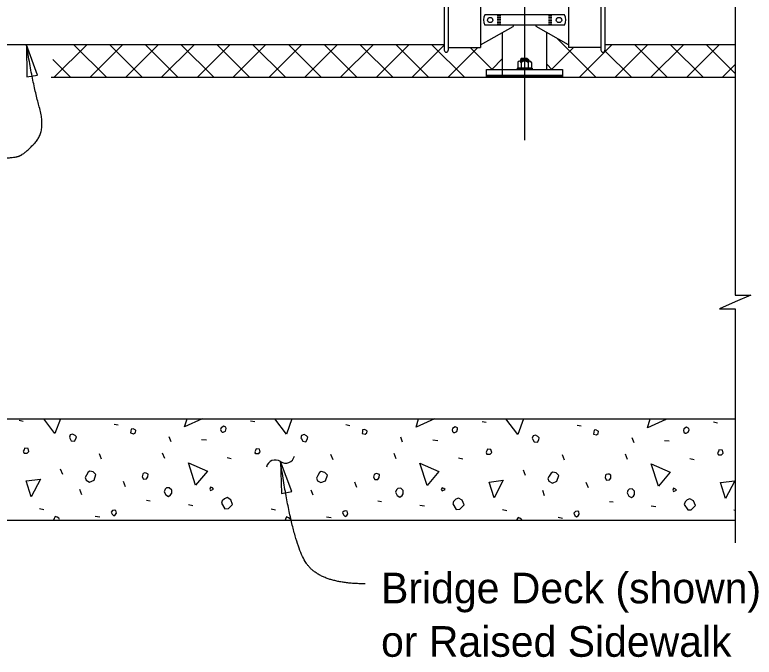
# Model space of a CAD drawing. Extents: x 110698 to 110915, y 110390 to 110472.
# Drawn here: x 110792.784 to 110797.653, y 110451.994 to 110456.224 of the extents above; entities that cross this region are included whole.
import ezdxf

# ---------------------------------------------------------------- set-up
doc = ezdxf.new("R2010")
doc.units = 0
for name, color, linetype in [('AdhocPoint_dp', 7, 'Continuous'), ('PlotBorder_dp', 7, 'Continuous'), ('SheetBorder_dp', 7, 'Continuous'), ('SheetLines_dp', 7, 'Continuous'), ('TextMisc', 7, 'Continuous')]:
    doc.layers.add(name, color=color, linetype=linetype)

msp = doc.modelspace()

# ---------------------------------------------------------------- linework, layer by layer
at = {"layer": 'AdhocPoint_dp'}
msp.add_line((110796.1408, 110464.1815), (110796.1408, 110455.3996), dxfattribs=at)
at = {"layer": 'PlotBorder_dp'}
msp.add_line((110796.1408, 110455.8731), (110796.1408, 110455.8724), dxfattribs=at)
for points in [[(110797.5278, 110458.8754), (110797.5278, 110457.8577), (110797.6311, 110457.8577), (110797.5278, 110457.8127), (110797.4245, 110457.7677), (110797.5278, 110457.7677), (110797.5278, 110455.8133)], [(110797.5278, 110455.8133), (110797.5278, 110454.3793), (110797.6311, 110454.3793), (110797.5278, 110454.3343), (110797.4245, 110454.2893), (110797.5278, 110454.2893), (110797.5278, 110452.7468)]]:
    msp.add_lwpolyline(points, dxfattribs=at)
for points in [[(110792.8618, 110456.0268), (110792.8634, 110455.8156), (110792.9329, 110455.8279)], [(110794.5338, 110453.2829), (110794.5399, 110453.0717), (110794.6091, 110453.0855)]]:
    msp.add_lwpolyline(points, close=True, dxfattribs=at)
for centre, start, end in [((110794.4992, 110453.2334), 55.4525, 167.1798), ((110794.5668, 110453.3316), 235.4525, 347.1798)]:
    msp.add_arc(centre, 0.0596, start, end, dxfattribs=at)
for points in [[(110792.5505, 110455.2798), (110792.7733, 110455.2763), (110792.8582, 110455.3152), (110792.9891, 110455.4639), (110792.9042, 110455.7614), (110792.8618, 110456.0267)], [(110795.0922, 110452.4775), (110794.8036, 110452.4775), (110794.6145, 110452.733), (110794.5338, 110453.2829)]]:
    msp.add_open_spline(points, degree=2, dxfattribs=at)
at = {"layer": 'SheetBorder_dp'}
for p, q in [((110796.35, 110456.0722), (110796.6089, 110455.8133)), ((110793.044, 110455.8133), (110793.2575, 110456.0268)), ((110793.1736, 110456.0268), (110793.3871, 110455.8133)), ((110793.2797, 110455.8133), (110793.4932, 110456.0268)), ((110793.4093, 110456.0268), (110793.6228, 110455.8133)), ((110793.5154, 110455.8133), (110793.7289, 110456.0268)), ((110793.645, 110456.0268), (110793.8585, 110455.8133)), ((110793.7511, 110455.8133), (110793.9646, 110456.0268)), ((110793.8807, 110456.0268), (110794.0942, 110455.8133)), ((110793.9868, 110455.8133), (110794.2003, 110456.0268)), ((110794.1164, 110456.0268), (110794.3299, 110455.8133)), ((110794.2225, 110455.8133), (110794.436, 110456.0268)), ((110794.3521, 110456.0268), (110794.5656, 110455.8133)), ((110794.4582, 110455.8133), (110794.6717, 110456.0268)), ((110794.5878, 110456.0268), (110794.8013, 110455.8133)), ((110794.6939, 110455.8133), (110794.9074, 110456.0268)), ((110794.8235, 110456.0268), (110795.0371, 110455.8133)), ((110794.9296, 110455.8133), (110795.1431, 110456.0268)), ((110795.0592, 110456.0268), (110795.2728, 110455.8133)), ((110795.1653, 110455.8133), (110795.3788, 110456.0268)), ((110795.2949, 110456.0268), (110795.5085, 110455.8133)), ((110795.401, 110455.8133), (110795.6114, 110456.0237)), ((110795.5306, 110456.0268), (110795.7442, 110455.8133)), ((110795.6367, 110455.8133), (110795.833, 110456.0096)), ((110795.7836, 110456.0096), (110795.9278, 110455.8653)), ((110796.3179, 110455.8653), (110796.4621, 110456.0096)), ((110796.5015, 110455.8133), (110796.715, 110456.0268)), ((110796.7372, 110455.8133), (110796.9507, 110456.0268)), ((110796.8668, 110456.0268), (110797.0803, 110455.8133)), ((110796.9729, 110455.8133), (110797.1864, 110456.0268)), ((110797.1025, 110456.0268), (110797.316, 110455.8133)), ((110797.2086, 110455.8133), (110797.4221, 110456.0268)), ((110797.3382, 110456.0268), (110797.5277, 110455.8373)), ((110796.6701, 110455.9878), (110796.8446, 110455.8133)), ((110793.034, 110455.9307), (110793.1514, 110455.8133)), ((110795.9245, 110455.8653), (110795.995, 110455.9358)), ((110796.1296, 110455.9348), (110796.1503, 110455.9348)), ((110796.1296, 110455.9251), (110796.1503, 110455.9251)), ((110796.2899, 110455.8966), (110796.3212, 110455.8653)), ((110797.4443, 110455.8133), (110797.5277, 110455.8967)), ((110795.8908, 110455.8202), (110796.3908, 110455.8202)), ((110795.8908, 110455.8167), (110796.3908, 110455.8167)), ((110792.8134, 110453.5542), (110792.8399, 110453.5489)), ((110793.4391, 110453.5294), (110793.4657, 110453.5241)), ((110794.3372, 110453.5507), (110794.3637, 110453.5453)), ((110794.963, 110453.5259), (110794.9895, 110453.5206)), ((110795.861, 110453.5471), (110795.8875, 110453.5418)), ((110797.3848, 110453.5436), (110797.4113, 110453.5383)), ((110796.4868, 110453.5224), (110796.5133, 110453.5171)), ((110793.8139, 110453.4128), (110793.8015, 110453.4464)), ((110794.0137, 110453.4287), (110794.0455, 110453.4251)), ((110795.3377, 110453.4092), (110795.3254, 110453.4428)), ((110796.8615, 110453.4057), (110796.8492, 110453.4393)), ((110795.5375, 110453.4251), (110795.5693, 110453.4216)), ((110797.0613, 110453.4216), (110797.0931, 110453.4181)), ((110793.3561, 110453.2979), (110793.3419, 110453.3332)), ((110793.7715, 110453.3032), (110793.7573, 110453.3385)), ((110794.8799, 110453.2943), (110794.8657, 110453.3297)), ((110795.2953, 110453.2996), (110795.2812, 110453.335)), ((110796.8191, 110453.2961), (110796.805, 110453.3314)), ((110794.1816, 110453.3102), (110794.2099, 110453.3032)), ((110795.7054, 110453.3067), (110795.7337, 110453.2996)), ((110796.4037, 110453.2908), (110796.3896, 110453.3261)), ((110797.2292, 110453.3032), (110797.2575, 110453.2961)), ((110793.0997, 110453.1971), (110793.0856, 110453.2325)), ((110796.1474, 110453.19), (110796.1332, 110453.2254)), ((110793.5134, 110453.1158), (110793.4993, 110453.1511)), ((110795.0372, 110453.1122), (110795.0231, 110453.1476)), ((110796.561, 110453.1087), (110796.5469, 110453.1441)), ((110793.2252, 110453.0645), (110793.2129, 110453.0981)), ((110794.7491, 110453.061), (110794.7367, 110453.0946)), ((110796.2729, 110453.0574), (110796.2605, 110453.091)), ((110793.6513, 110453.0274), (110793.676, 110453.0239)), ((110793.9271, 110452.9991), (110793.9571, 110452.9938)), ((110795.1751, 110453.0239), (110795.1998, 110453.0203)), ((110795.4509, 110452.9956), (110795.4809, 110452.9903)), ((110796.6989, 110453.0203), (110796.7237, 110453.0168)), ((110796.9747, 110452.992), (110797.0047, 110452.9867)), ((110792.9477, 110452.9744), (110792.976, 110452.9673)), ((110794.4715, 110452.9708), (110794.4998, 110452.9638)), ((110795.9953, 110452.9673), (110796.0236, 110452.9602)), ((110797.5192, 110452.9638), (110797.5277, 110452.9616)), ((110793.3136, 110452.9231), (110793.3437, 110452.9178)), ((110794.0638, 110452.8966), (110794.0632, 110452.8983)), ((110794.8375, 110452.9196), (110794.8675, 110452.9143)), ((110796.3613, 110452.916), (110796.3913, 110452.9107))]:
    msp.add_line(p, q, dxfattribs=at)
msp.add_lwpolyline([(110795.8908, 110455.8237), (110796.3908, 110455.8237), (110796.3908, 110455.8133), (110795.8908, 110455.8133)], close=True, dxfattribs=at)
for points in [[(110793.0485, 110453.4676), (110792.9758, 110453.5632)], [(110793.0842, 110453.5632), (110793.0485, 110453.4676)], [(110793.9023, 110453.5118), (110793.9181, 110453.5632)], [(110794.0169, 110453.5632), (110793.9023, 110453.5118)], [(110794.5723, 110453.464), (110794.4969, 110453.5632)], [(110794.6094, 110453.5632), (110794.5723, 110453.464)], [(110795.4261, 110453.5082), (110795.443, 110453.5632)], [(110795.5475, 110453.5632), (110795.5481, 110453.563), (110795.4261, 110453.5082)], [(110796.0961, 110453.4605), (110796.018, 110453.5632)], [(110796.1345, 110453.5632), (110796.0961, 110453.4605)], [(110796.9499, 110453.5047), (110796.9679, 110453.5632)], [(110797.0624, 110453.5632), (110797.0719, 110453.5595), (110796.9499, 110453.5047)], [(110793.547, 110453.4711), (110793.5664, 110453.4658), (110793.5788, 110453.4746), (110793.5806, 110453.487), (110793.577, 110453.4905), (110793.5629, 110453.4976), (110793.5505, 110453.4959), (110793.5487, 110453.4835), (110793.547, 110453.4711)], [(110794.1498, 110453.4764), (110794.1569, 110453.4764), (110794.171, 110453.4835), (110794.1763, 110453.4994), (110794.1745, 110453.5082), (110794.1604, 110453.5153), (110794.1427, 110453.5047), (110794.1392, 110453.4941), (110794.1427, 110453.4835), (110794.1498, 110453.4764)], [(110795.0708, 110453.4676), (110795.0902, 110453.4623), (110795.1026, 110453.4711), (110795.1044, 110453.4835), (110795.1008, 110453.487), (110795.0867, 110453.4941), (110795.0743, 110453.4923), (110795.0726, 110453.4799), (110795.0708, 110453.4676)], [(110795.6736, 110453.4729), (110795.6807, 110453.4729), (110795.6948, 110453.4799), (110795.7001, 110453.4959), (110795.6984, 110453.5047), (110795.6842, 110453.5118), (110795.6665, 110453.5012), (110795.663, 110453.4905), (110795.6665, 110453.4799), (110795.6736, 110453.4729)], [(110796.5946, 110453.464), (110796.6141, 110453.4587), (110796.6264, 110453.4676), (110796.6282, 110453.4799), (110796.6247, 110453.4835), (110796.6105, 110453.4905), (110796.5981, 110453.4888), (110796.5964, 110453.4764), (110796.5946, 110453.464)], [(110797.1974, 110453.4693), (110797.2045, 110453.4693), (110797.2186, 110453.4764), (110797.2239, 110453.4923), (110797.2222, 110453.5012), (110797.208, 110453.5082), (110797.1903, 110453.4976), (110797.1868, 110453.487), (110797.1903, 110453.4764), (110797.1974, 110453.4693)], [(110793.1475, 110453.4357), (110793.1563, 110453.4198), (110793.1775, 110453.4163), (110793.1864, 110453.4322), (110793.1899, 110453.4464), (110793.1811, 110453.4552), (110793.1651, 110453.464), (110793.1492, 110453.4587), (110793.1439, 110453.4428), (110793.1475, 110453.4357)], [(110794.6713, 110453.4322), (110794.6801, 110453.4163), (110794.7013, 110453.4128), (110794.7102, 110453.4287), (110794.7137, 110453.4428), (110794.7049, 110453.4517), (110794.689, 110453.4605), (110794.673, 110453.4552), (110794.6677, 110453.4393), (110794.6713, 110453.4322)], [(110796.1951, 110453.4287), (110796.2039, 110453.4128), (110796.2251, 110453.4092), (110796.234, 110453.4251), (110796.2375, 110453.4393), (110796.2287, 110453.4481), (110796.2128, 110453.457), (110796.1969, 110453.4517), (110796.1916, 110453.4357), (110796.1951, 110453.4287)], [(110792.8452, 110453.3385), (110792.8664, 110453.3385), (110792.877, 110453.3491), (110792.8717, 110453.3686), (110792.8487, 110453.3703), (110792.8452, 110453.3597), (110792.8399, 110453.3509), (110792.8452, 110453.3385), (110792.8416, 110453.3421)], [(110794.369, 110453.335), (110794.3902, 110453.335), (110794.4008, 110453.3456), (110794.3955, 110453.365), (110794.3725, 110453.3668), (110794.369, 110453.3562), (110794.3637, 110453.3474), (110794.369, 110453.335), (110794.3655, 110453.3385)], [(110795.8928, 110453.3314), (110795.914, 110453.3314), (110795.9246, 110453.3421), (110795.9193, 110453.3615), (110795.8963, 110453.3633), (110795.8928, 110453.3527), (110795.8875, 110453.3438), (110795.8928, 110453.3314), (110795.8893, 110453.335)], [(110797.4166, 110453.3279), (110797.4378, 110453.3279), (110797.4484, 110453.3385), (110797.4431, 110453.358), (110797.4202, 110453.3597), (110797.4166, 110453.3491), (110797.4113, 110453.3403), (110797.4166, 110453.3279), (110797.4131, 110453.3314)], [(110793.9748, 110453.1282), (110793.9271, 110453.2749), (110794.0526, 110453.2201), (110793.9748, 110453.1282)], [(110795.4986, 110453.1246), (110795.4509, 110453.2713), (110795.5764, 110453.2165), (110795.4986, 110453.1246)], [(110797.0224, 110453.1211), (110796.9747, 110453.2678), (110797.1002, 110453.213), (110797.0224, 110453.1211)], [(110793.2535, 110453.16), (110793.2765, 110453.1476), (110793.3066, 110453.16), (110793.3189, 110453.1971), (110793.3013, 110453.2148), (110793.2783, 110453.2201), (110793.2677, 110453.213), (110793.2553, 110453.1936), (110793.2465, 110453.1777), (110793.2535, 110453.16)], [(110793.623, 110453.183), (110793.6318, 110453.167), (110793.6513, 110453.1688), (110793.6601, 110453.1812), (110793.6619, 110453.2006), (110793.6495, 110453.2059), (110793.6407, 110453.2077), (110793.6301, 110453.2042), (110793.6265, 110453.2006), (110793.623, 110453.183)], [(110794.7773, 110453.1564), (110794.8003, 110453.1441), (110794.8304, 110453.1564), (110794.8428, 110453.1936), (110794.8251, 110453.2112), (110794.8021, 110453.2165), (110794.7915, 110453.2095), (110794.7791, 110453.19), (110794.7703, 110453.1741), (110794.7773, 110453.1564)], [(110795.1468, 110453.1794), (110795.1556, 110453.1635), (110795.1751, 110453.1653), (110795.1839, 110453.1777), (110795.1857, 110453.1971), (110795.1733, 110453.2024), (110795.1645, 110453.2042), (110795.1539, 110453.2006), (110795.1503, 110453.1971), (110795.1468, 110453.1794)], [(110796.3012, 110453.1529), (110796.3241, 110453.1405), (110796.3542, 110453.1529), (110796.3666, 110453.19), (110796.3489, 110453.2077), (110796.3259, 110453.213), (110796.3153, 110453.2059), (110796.3029, 110453.1865), (110796.2941, 110453.1706), (110796.3012, 110453.1529)], [(110796.6706, 110453.1759), (110796.6795, 110453.16), (110796.6989, 110453.1617), (110796.7077, 110453.1741), (110796.7095, 110453.1936), (110796.6971, 110453.1989), (110796.6883, 110453.2006), (110796.6777, 110453.1971), (110796.6742, 110453.1936), (110796.6706, 110453.1759)], [(110792.8929, 110453.0504), (110792.8593, 110453.1547), (110792.953, 110453.167), (110792.8929, 110453.0504)], [(110795.9405, 110453.0433), (110795.9069, 110453.1476), (110796.0006, 110453.16), (110795.9405, 110453.0433)], [(110797.4644, 110453.0398), (110797.4308, 110453.1441), (110797.5245, 110453.1564), (110797.4644, 110453.0398)], [(110793.768, 110453.084), (110793.7786, 110453.0627), (110793.7962, 110453.0521), (110793.8104, 110453.0627), (110793.8174, 110453.0734), (110793.8174, 110453.0946), (110793.8015, 110453.1105), (110793.7821, 110453.1087), (110793.7733, 110453.0999), (110793.768, 110453.084)], [(110794.0738, 110453.0928), (110794.0932, 110453.1016), (110794.0861, 110453.1087), (110794.0738, 110453.114), (110794.0685, 110453.1016), (110794.0738, 110453.0928)], [(110795.2918, 110453.0804), (110795.3024, 110453.0592), (110795.3201, 110453.0486), (110795.3342, 110453.0592), (110795.3413, 110453.0698), (110795.3413, 110453.091), (110795.3254, 110453.1069), (110795.3059, 110453.1052), (110795.2971, 110453.0963), (110795.2918, 110453.0804)], [(110795.5976, 110453.0893), (110795.617, 110453.0981), (110795.61, 110453.1052), (110795.5976, 110453.1105), (110795.5923, 110453.0981), (110795.5976, 110453.0893)], [(110796.8156, 110453.0769), (110796.8262, 110453.0557), (110796.8439, 110453.0451), (110796.858, 110453.0557), (110796.8651, 110453.0663), (110796.8651, 110453.0875), (110796.8492, 110453.1034), (110796.8297, 110453.1016), (110796.8209, 110453.0928), (110796.8156, 110453.0769)], [(110797.1214, 110453.0857), (110797.1409, 110453.0946), (110797.1338, 110453.1016), (110797.1214, 110453.1069), (110797.1161, 110453.0946), (110797.1214, 110453.0857)], [(110794.1445, 110453.0079), (110794.1675, 110452.9708), (110794.1904, 110452.9726), (110794.1993, 110452.9814), (110794.2187, 110453.0009), (110794.2064, 110453.0309), (110794.1816, 110453.0451), (110794.1639, 110453.038), (110794.1498, 110453.0239), (110794.1445, 110453.0079)], [(110795.6683, 110453.0044), (110795.6913, 110452.9673), (110795.7143, 110452.9691), (110795.7231, 110452.9779), (110795.7425, 110452.9973), (110795.7302, 110453.0274), (110795.7054, 110453.0415), (110795.6877, 110453.0345), (110795.6736, 110453.0203), (110795.6683, 110453.0044)], [(110797.1921, 110453.0009), (110797.2151, 110452.9638), (110797.2381, 110452.9655), (110797.2469, 110452.9744), (110797.2664, 110452.9938), (110797.254, 110453.0239), (110797.2292, 110453.038), (110797.2116, 110453.0309), (110797.1974, 110453.0168), (110797.1921, 110453.0009)], [(110793.425, 110452.9355), (110793.4356, 110452.9249), (110793.4462, 110452.9319), (110793.4533, 110452.9425), (110793.4498, 110452.9602), (110793.4409, 110452.962), (110793.4285, 110452.9602), (110793.4179, 110452.9496), (110793.425, 110452.9355)], [(110794.9488, 110452.9319), (110794.9594, 110452.9213), (110794.97, 110452.9284), (110794.9771, 110452.939), (110794.9736, 110452.9567), (110794.9647, 110452.9584), (110794.9524, 110452.9567), (110794.9417, 110452.9461), (110794.9488, 110452.9319)], [(110796.4726, 110452.9284), (110796.4832, 110452.9178), (110796.4938, 110452.9249), (110796.5009, 110452.9355), (110796.4974, 110452.9531), (110796.4885, 110452.9549), (110796.4762, 110452.9531), (110796.4656, 110452.9425), (110796.4726, 110452.9284)], [(110793.0773, 110452.8966), (110793.0785, 110452.9001), (110793.0732, 110452.909), (110793.0626, 110452.916), (110793.0502, 110452.9213), (110793.0432, 110452.9072), (110793.0396, 110452.8966)], [(110794.6023, 110452.8966), (110794.597, 110452.9054), (110794.5864, 110452.9125), (110794.5741, 110452.9178), (110794.567, 110452.9036), (110794.5646, 110452.8966)], [(110796.124, 110452.8966), (110796.1208, 110452.9019), (110796.1102, 110452.909), (110796.0979, 110452.9143), (110796.0908, 110452.9001), (110796.0896, 110452.8966)]]:
    msp.add_lwpolyline(points, dxfattribs=at)
at = {"layer": 'SheetLines_dp'}
for p, q in [((110793.0238, 110455.8133), (110797.5278, 110455.8133)), ((110774.7539, 110453.5632), (110797.5277, 110453.5632)), ((110774.7539, 110452.8966), (110797.5277, 110452.8966))]:
    msp.add_line(p, q, dxfattribs=at)
at = {"layer": 'TextMisc'}
for p, q in [((110795.6114, 110456.3014), (110795.6114, 110455.9917)), ((110795.6383, 110456.3014), (110795.6383, 110455.9917)), ((110796.6433, 110456.3014), (110796.6433, 110455.9917)), ((110796.6701, 110456.3014), (110796.6701, 110455.9917)), ((110795.8512, 110456.2818), (110795.8512, 110456.0096)), ((110796.4303, 110456.2818), (110796.4303, 110456.0096)), ((110796.4031, 110456.2245), (110795.8784, 110456.2245)), ((110795.9608, 110456.2167), (110795.9842, 110456.2167)), ((110795.9608, 110456.2071), (110795.9842, 110456.2071)), ((110796.3208, 110456.2167), (110796.2973, 110456.2167)), ((110796.3208, 110456.2071), (110796.2973, 110456.2071)), ((110796.4031, 110456.1567), (110795.8784, 110456.1567)), ((110795.9608, 110456.1963), (110795.9842, 110456.1963)), ((110795.9608, 110456.1845), (110795.9842, 110456.1845)), ((110795.9608, 110456.1727), (110795.9842, 110456.1727)), ((110795.9608, 110456.1629), (110795.9842, 110456.1629)), ((110796.3208, 110456.1963), (110796.2973, 110456.1963)), ((110796.3208, 110456.1845), (110796.2973, 110456.1845)), ((110796.3208, 110456.1727), (110796.2973, 110456.1727)), ((110796.3208, 110456.1629), (110796.2973, 110456.1629)), ((110795.8512, 110456.0277), (110796.0652, 110456.1463)), ((110795.995, 110455.8133), (110795.995, 110456.1073)), ((110796.4303, 110456.0277), (110796.2164, 110456.1463)), ((110796.2866, 110455.8653), (110796.2866, 110456.1073)), ((110795.6114, 110456.0268), (110786.6701, 110456.0268)), ((110795.6383, 110456.0096), (110795.8512, 110456.0096)), ((110796.6433, 110456.0096), (110796.4303, 110456.0096)), ((110797.5278, 110456.0268), (110796.6701, 110456.0268)), ((110796.0953, 110455.9101), (110796.0953, 110455.8724)), ((110796.1748, 110455.9187), (110796.1067, 110455.9187)), ((110796.1247, 110455.9397), (110796.115, 110455.93)), ((110796.115, 110455.93), (110796.115, 110455.9187)), ((110796.115, 110455.93), (110796.1665, 110455.93)), ((110796.118, 110455.9103), (110796.118, 110455.8724)), ((110796.1247, 110455.9397), (110796.1552, 110455.9397)), ((110796.1552, 110455.9397), (110796.1665, 110455.93)), ((110796.1634, 110455.9103), (110796.1634, 110455.8724)), ((110796.1665, 110455.93), (110796.1665, 110455.9187)), ((110796.1861, 110455.9101), (110796.1861, 110455.8724)), ((110796.0911, 110455.8724), (110796.0911, 110455.8653)), ((110796.0911, 110455.8724), (110796.1905, 110455.8724)), ((110796.1861, 110455.8724), (110796.0953, 110455.8724)), ((110796.1905, 110455.8724), (110796.1905, 110455.8653)), ((110796.021, 110455.8237), (110796.2606, 110455.8237))]:
    msp.add_line(p, q, dxfattribs=at)
msp.add_lwpolyline([(110795.8908, 110455.8653), (110796.3908, 110455.8653), (110796.3908, 110455.8237), (110795.8908, 110455.8237)], close=True, dxfattribs=at)
for centre, radius, start, end in [((110795.6249, 110455.9915), 0.0134, 180, 0), ((110796.6566, 110455.9915), 0.0134, 180, 0), ((110796.1068, 110455.907), 0.0118, 16.5986, 164.7005), ((110796.1408, 110455.884), 0.0347, 49.2015, 130.7985), ((110796.1748, 110455.907), 0.0118, 15.1506, 163.5042)]:
    msp.add_arc(centre, radius, start, end, dxfattribs=at)
for centre, major_axis, start_param, end_param in [((110795.9475, 110456.1905), (-0.0776, 0), 5.810211, 6.75616), ((110796.334, 110456.1905), (0.0776, 0), 5.810211, 6.75616), ((110795.9276, 110456.1925), (0.146, 0), 5.947976, 6.024627), ((110796.354, 110456.1925), (-0.146, 0), 0.258558, 0.335209)]:
    msp.add_ellipse(centre, major_axis=major_axis, ratio=0.957868, start_param=start_param, end_param=end_param, dxfattribs=at)
for centre, major_axis in [((110795.9142, 110456.19), (0.0178, 0)), ((110796.3673, 110456.19), (-0.0178, 0))]:
    msp.add_ellipse(centre, major_axis=major_axis, ratio=0.957868, dxfattribs=at)

# ---------------------------------------------------------------- texts
at = {"layer": 'PlotBorder_dp'}
for s, p in [('Bridge Deck (shown)', (110795.196, 110452.3491)), ('or Raised Sidewalk', (110795.196, 110451.9971))]:
    msp.add_text(s, height=0.2016, dxfattribs=at).set_placement(p)

doc.saveas('drawing.dxf')
